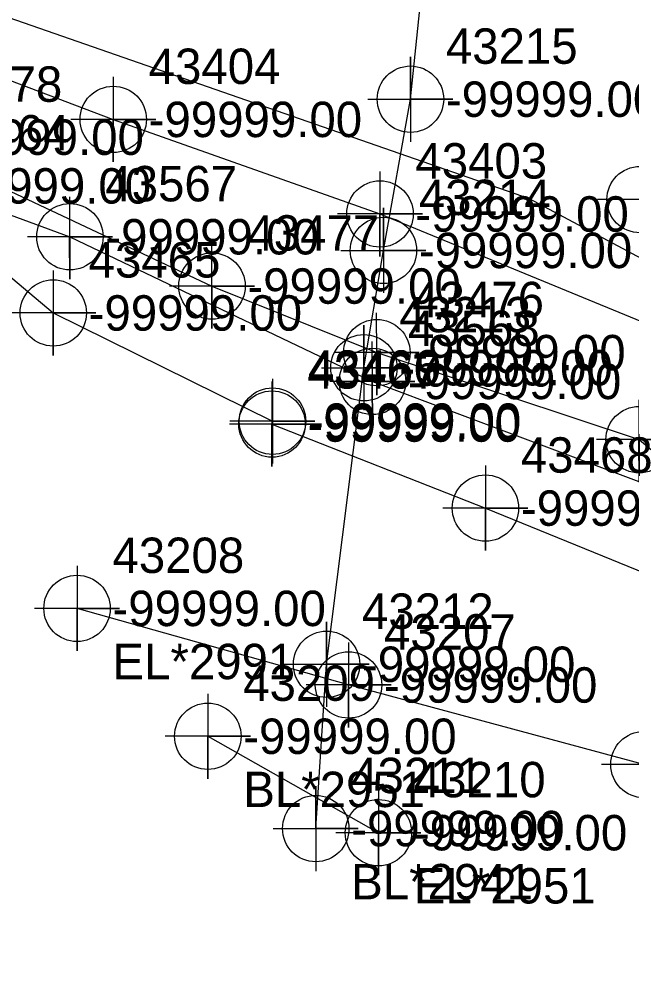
# Model space of a CAD drawing. Extents: x 2083698 to 2094313, y 743246 to 752873.
# Drawn here: x 2092625 to 2092668.3, y 746814.5 to 746882.2 of the extents above; entities that cross this region are included whole.
import ezdxf

# ---------------------------------------------------------------- set-up
doc = ezdxf.new("R2010")
doc.units = 0
for name, color, linetype in [('COGO Default Chain', 7, 'Continuous'), ('COGO Default Curve', 7, 'Continuous'), ('COGO Default Point Number', 7, 'Continuous'), ('Exist Property Iron Pin Leader', 7, 'Continuous'), ('Exist Property Iron Pin Text', 7, 'Continuous'), ('Exist Property Line', 7, 'Continuous'), ('Exist Property Monument Leader', 7, 'Continuous'), ('Exist Property Monument Text', 7, 'Continuous'), ('Exist Right of Way Easement Line', 7, 'Continuous'), ('Exist Right of Way Line', 7, 'Continuous'), ('Exist Right of Way Line Leader', 7, 'Continuous'), ('Exist Right of Way Line Text', 7, 'Continuous'), ('Exist Right of Way Width CELL', 7, 'Continuous'), ('Exist Utilities Gas UG Line SUE LOS B', 7, 'Continuous'), ('Exist Utilities Power UG Cable SUE LOS B', 7, 'Continuous'), ('Exist Utilities Telephone UG Conduit SUE LOS B', 7, 'Continuous'), ('Exist Utilities TV UG Cable SUE LOS C', 7, 'Continuous'), ('Exist Utilities Water UG Line SUE LOS B', 7, 'Continuous'), ('Old_Level_20', 7, 'Continuous'), ('Scratch_Level_2', 7, 'Continuous')]:
    doc.layers.add(name, color=color, linetype=linetype)

msp = doc.modelspace()

# ---------------------------------------------------------------- linework, layer by layer
at = {"layer": 'COGO Default Curve'}
for points in [[(2092649.648, 746876.574), (2092655.648, 746876.574), (2092652.648, 746876.574), (2092652.648, 746879.574), (2092652.648, 746873.574)], [(2092647.74, 746865.894), (2092653.74, 746865.894), (2092650.74, 746865.894), (2092650.74, 746868.894), (2092650.74, 746862.894)], [(2092646.365, 746857.61), (2092652.365, 746857.61), (2092649.365, 746857.61), (2092649.365, 746860.61), (2092649.365, 746854.61)], [(2092643.729, 746836.672), (2092649.729, 746836.672), (2092646.729, 746836.672), (2092646.729, 746839.672), (2092646.729, 746833.672)], [(2092642.967, 746825.07), (2092648.967, 746825.07), (2092645.967, 746825.07), (2092645.967, 746828.07), (2092645.967, 746822.07)]]:
    msp.add_lwpolyline(points, dxfattribs=at)
for centre in [(2092652.648, 746876.574), (2092650.74, 746865.894), (2092649.365, 746857.61), (2092646.729, 746836.672), (2092645.967, 746825.07)]:
    msp.add_circle(centre, 2.344, dxfattribs=at)
at = {"layer": 'COGO Default Point Number'}
for points in [[(2092629.125, 746843.616), (2092629.125, 746837.616), (2092629.125, 746840.616), (2092632.125, 746840.616), (2092626.125, 746840.616)], [(2092648.281, 746838.209), (2092648.281, 746832.209), (2092648.281, 746835.209), (2092651.281, 746835.209), (2092645.281, 746835.209)], [(2092669.124, 746832.59), (2092669.124, 746826.59), (2092669.124, 746829.59), (2092672.124, 746829.59), (2092666.124, 746829.59)]]:
    msp.add_lwpolyline(points, dxfattribs=at)
for centre in [(2092629.125, 746840.616), (2092648.281, 746835.209), (2092669.124, 746829.59)]:
    msp.add_circle(centre, 2.344, dxfattribs=at)
at = {"layer": 'Exist Property Iron Pin Text'}
for points in [[(2092631.679, 746878.147), (2092631.679, 746872.147), (2092631.679, 746875.147), (2092634.679, 746875.147), (2092628.679, 746875.147)], [(2092650.497, 746871.469), (2092650.497, 746865.469), (2092650.497, 746868.469), (2092653.497, 746868.469), (2092647.497, 746868.469)], [(2092627.444, 746864.48), (2092627.444, 746858.48), (2092627.444, 746861.48), (2092630.444, 746861.48), (2092624.444, 746861.48)], [(2092642.878, 746856.635), (2092642.878, 746850.635), (2092642.878, 746853.635), (2092645.878, 746853.635), (2092639.878, 746853.635)], [(2092642.913, 746856.838), (2092642.913, 746850.838), (2092642.913, 746853.838), (2092645.913, 746853.838), (2092639.913, 746853.838)], [(2092657.938, 746850.699), (2092657.938, 746844.699), (2092657.938, 746847.699), (2092660.938, 746847.699), (2092654.938, 746847.699)], [(2092638.352, 746834.588), (2092638.352, 746828.588), (2092638.352, 746831.588), (2092641.352, 746831.588), (2092635.352, 746831.588)], [(2092650.389, 746827.778), (2092650.389, 746821.778), (2092650.389, 746824.778), (2092653.389, 746824.778), (2092647.389, 746824.778)]]:
    msp.add_lwpolyline(points, dxfattribs=at)
for centre in [(2092631.679, 746875.147), (2092650.497, 746868.469), (2092627.444, 746861.48), (2092642.878, 746853.635), (2092642.913, 746853.838), (2092657.938, 746847.699), (2092638.352, 746831.588), (2092650.389, 746824.778)]:
    msp.add_circle(centre, 2.344, dxfattribs=at)
at = {"layer": 'Exist Right of Way Line Text'}
for points in [[(2092668.818, 746872.299), (2092668.851, 746866.484), (2092668.834, 746869.484), (2092671.851, 746869.484), (2092665.851, 746869.484)], [(2092628.587, 746869.674), (2092628.62, 746863.859), (2092628.603, 746866.859), (2092631.62, 746866.859), (2092625.62, 746866.859)], [(2092638.612, 746866.195), (2092638.645, 746860.38), (2092638.628, 746863.38), (2092641.645, 746863.38), (2092635.645, 746863.38)], [(2092650.24, 746861.492), (2092650.273, 746855.677), (2092650.256, 746858.677), (2092653.273, 746858.677), (2092647.273, 746858.677)], [(2092649.935, 746859.458), (2092649.968, 746853.643), (2092649.951, 746856.643), (2092652.968, 746856.643), (2092646.968, 746856.643)], [(2092668.751, 746855.347), (2092668.784, 746849.532), (2092668.767, 746852.532), (2092671.784, 746852.532), (2092665.784, 746852.532)]]:
    msp.add_lwpolyline(points, dxfattribs=at)
for centre in [(2092668.851, 746869.484), (2092628.62, 746866.859), (2092638.645, 746863.38), (2092650.273, 746858.677), (2092649.968, 746856.643), (2092668.784, 746852.532)]:
    msp.add_circle(centre, 2.344, dxfattribs=at)
at = {"layer": 'Exist Utilities Gas UG Line SUE LOS B'}
msp.add_lwpolyline([(2092645.967, 746825.07), (2092646.729, 746836.672), (2092649.365, 746857.61), (2092650.74, 746865.894), (2092652.648, 746876.574), (2092655.206, 746901.31), (2092673.784, 746903.506), (2092702.577, 746903.705), (2092714.098, 746904.55), (2092717.513, 746904.633), (2092725.806, 746901.086)], dxfattribs=at)
at = {"layer": 'Exist Utilities Power UG Cable SUE LOS B'}
msp.add_line((2092638.352, 746831.588), (2092650.389, 746824.778), dxfattribs=at)
for points in [[(2092330.943, 746990.586), (2092329.394, 746986.815), (2092327.753, 746982.584), (2092328.042, 746981.03), (2092339.046, 746977.269), (2092359.63, 746969.333), (2092380.809, 746962.315), (2092406.102, 746952.154), (2092435.178, 746941.743), (2092450.157, 746936.165), (2092473.813, 746926.615), (2092482.34, 746922.858), (2092495.481, 746919.21), (2092516.288, 746911.989), (2092530.903, 746905.033), (2092549.144, 746899.745), (2092580.962, 746889.134), (2092599.163, 746879.223), (2092616.794, 746870.453), (2092627.444, 746861.48), (2092642.913, 746853.838), (2092642.878, 746853.635), (2092657.938, 746847.699), (2092676.244, 746840.235)], [(2092521.964, 746918.605), (2092522.11, 746916.299), (2092533.307, 746910.623), (2092549.07, 746903.13), (2092557.129, 746899.703), (2092581.402, 746893.073), (2092601.213, 746886.722), (2092631.679, 746875.147), (2092650.497, 746868.469), (2092673.074, 746859.188), (2092675.951, 746854.191), (2092672.442, 746847.502), (2092676.07, 746845.26)]]:
    msp.add_lwpolyline(points, dxfattribs=at)
at = {"layer": 'Exist Utilities Telephone UG Conduit SUE LOS B'}
for points in [[(2092179.973, 747040.693), (2092189.433, 747036.495), (2092208.378, 747029.171), (2092230.748, 747017.189), (2092261.723, 747004.905), (2092280.547, 746997.383), (2092300.091, 746989.104), (2092311.634, 746984.868), (2092339.079, 746976.561), (2092379.376, 746961.073), (2092406.464, 746951.417), (2092420.918, 746946.429), (2092436.276, 746938.067), (2092449.53, 746933.012), (2092472.836, 746924.71), (2092494.208, 746915.081), (2092513.106, 746905.863), (2092531.547, 746898.807), (2092546.582, 746892.645), (2092568.751, 746886.508), (2092598.56, 746877.939), (2092628.62, 746866.859), (2092649.968, 746856.643), (2092673.024, 746847.988)], [(2092450.45, 746937.817), (2092474.08, 746928.683), (2092495.622, 746920.515), (2092495.689, 746920.405), (2092515.827, 746912.958), (2092531.048, 746907.97), (2092556.414, 746898.103), (2092580.535, 746889.346), (2092599.791, 746881.48), (2092616.286, 746873.89), (2092638.645, 746863.38), (2092650.273, 746858.677), (2092668.784, 746852.532), (2092673.162, 746848.859)]]:
    msp.add_lwpolyline(points, dxfattribs=at)
at = {"layer": 'Exist Utilities TV UG Cable SUE LOS C'}
msp.add_lwpolyline([(2092630.812, 747042.398), (2092606.216, 747003.257), (2092583.171, 746896.687), (2092661.023, 746869.561), (2092698.013, 746849.797), (2092746.907, 746814.46)], dxfattribs=at)
at = {"layer": 'Exist Utilities Water UG Line SUE LOS B'}
msp.add_lwpolyline([(2092694.131, 746935.26), (2092694.002, 746907.958), (2092694.635, 746899.3), (2092695.079, 746885.978), (2092694.184, 746874.065), (2092690.789, 746850.793), (2092684.446, 746838.294), (2092675.731, 746829.677), (2092669.124, 746829.59), (2092648.281, 746835.209), (2092629.125, 746840.616)], dxfattribs=at)

# ---------------------------------------------------------------- texts
at = {"layer": 'COGO Default Chain'}
for p in [(2092655.148, 746875.324), (2092653.24, 746864.644), (2092651.865, 746856.36), (2092649.229, 746835.422), (2092648.467, 746823.82)]:
    msp.add_text('-99999.00', height=2.5, dxfattribs=at).set_placement(p)
at = {"layer": 'Exist Property Iron Pin Leader'}
for s, p in [('43404', (2092634.179, 746877.647)), ('43464', (2092619.294, 746872.953)), ('43403', (2092652.997, 746870.969)), ('43465', (2092629.944, 746863.98)), ('43467', (2092645.378, 746856.135)), ('43466', (2092645.413, 746856.338)), ('43468', (2092660.438, 746850.199)), ('43209', (2092640.852, 746834.088)), ('43210', (2092652.889, 746827.278))]:
    msp.add_text(s, height=2.5, dxfattribs=at).set_placement(p)
at = {"layer": 'Exist Property Line'}
for p in [(2092631.625, 746839.366), (2092650.781, 746833.959)]:
    msp.add_text('-99999.00', height=2.5, dxfattribs=at).set_placement(p)
at = {"layer": 'Exist Property Monument Leader'}
for s, p in [('BL*2951', (2092640.852, 746826.588)), ('EL*2951', (2092652.889, 746819.778))]:
    msp.add_text(s, height=2.5, dxfattribs=at).set_placement(p)
at = {"layer": 'Exist Property Monument Text'}
for p in [(2092634.179, 746873.897), (2092619.294, 746869.203), (2092652.997, 746867.219), (2092629.944, 746860.23), (2092645.413, 746852.588), (2092645.378, 746852.385), (2092660.438, 746846.449), (2092640.852, 746830.338), (2092652.889, 746823.528)]:
    msp.add_text('-99999.00', height=2.5, dxfattribs=at).set_placement(p)
at = {"layer": 'Exist Right of Way Easement Line'}
msp.add_text('BL*2941', height=2.5, dxfattribs=at).set_placement((2092648.467, 746820.07))
at = {"layer": 'Exist Right of Way Line'}
for s, p in [('43208', (2092631.625, 746843.116)), ('43207', (2092650.781, 746837.709))]:
    msp.add_text(s, height=2.5, dxfattribs=at).set_placement(p)
at = {"layer": 'Exist Right of Way Line Leader'}
for s, p in [('43478', (2092618.786, 746876.39)), ('43567', (2092631.12, 746869.359)), ('43477', (2092641.145, 746865.88)), ('43476', (2092652.773, 746861.177)), ('43568', (2092652.468, 746859.143))]:
    msp.add_text(s, height=2.5, dxfattribs=at).set_placement(p)
at = {"layer": 'Exist Right of Way Width CELL'}
msp.add_text('EL*2991', height=2.5, dxfattribs=at).set_placement((2092631.625, 746835.616))
at = {"layer": 'Old_Level_20'}
for s, p in [('43215', (2092655.148, 746879.074)), ('43214', (2092653.24, 746868.394)), ('43213', (2092651.865, 746860.11)), ('43212', (2092649.229, 746839.172)), ('43211', (2092648.467, 746827.57))]:
    msp.add_text(s, height=2.5, dxfattribs=at).set_placement(p)
at = {"layer": 'Scratch_Level_2'}
for p in [(2092618.786, 746872.64), (2092631.12, 746865.609), (2092641.145, 746862.13), (2092652.773, 746857.427), (2092652.468, 746855.393)]:
    msp.add_text('-99999.00', height=2.5, dxfattribs=at).set_placement(p)

doc.saveas('drawing.dxf')
